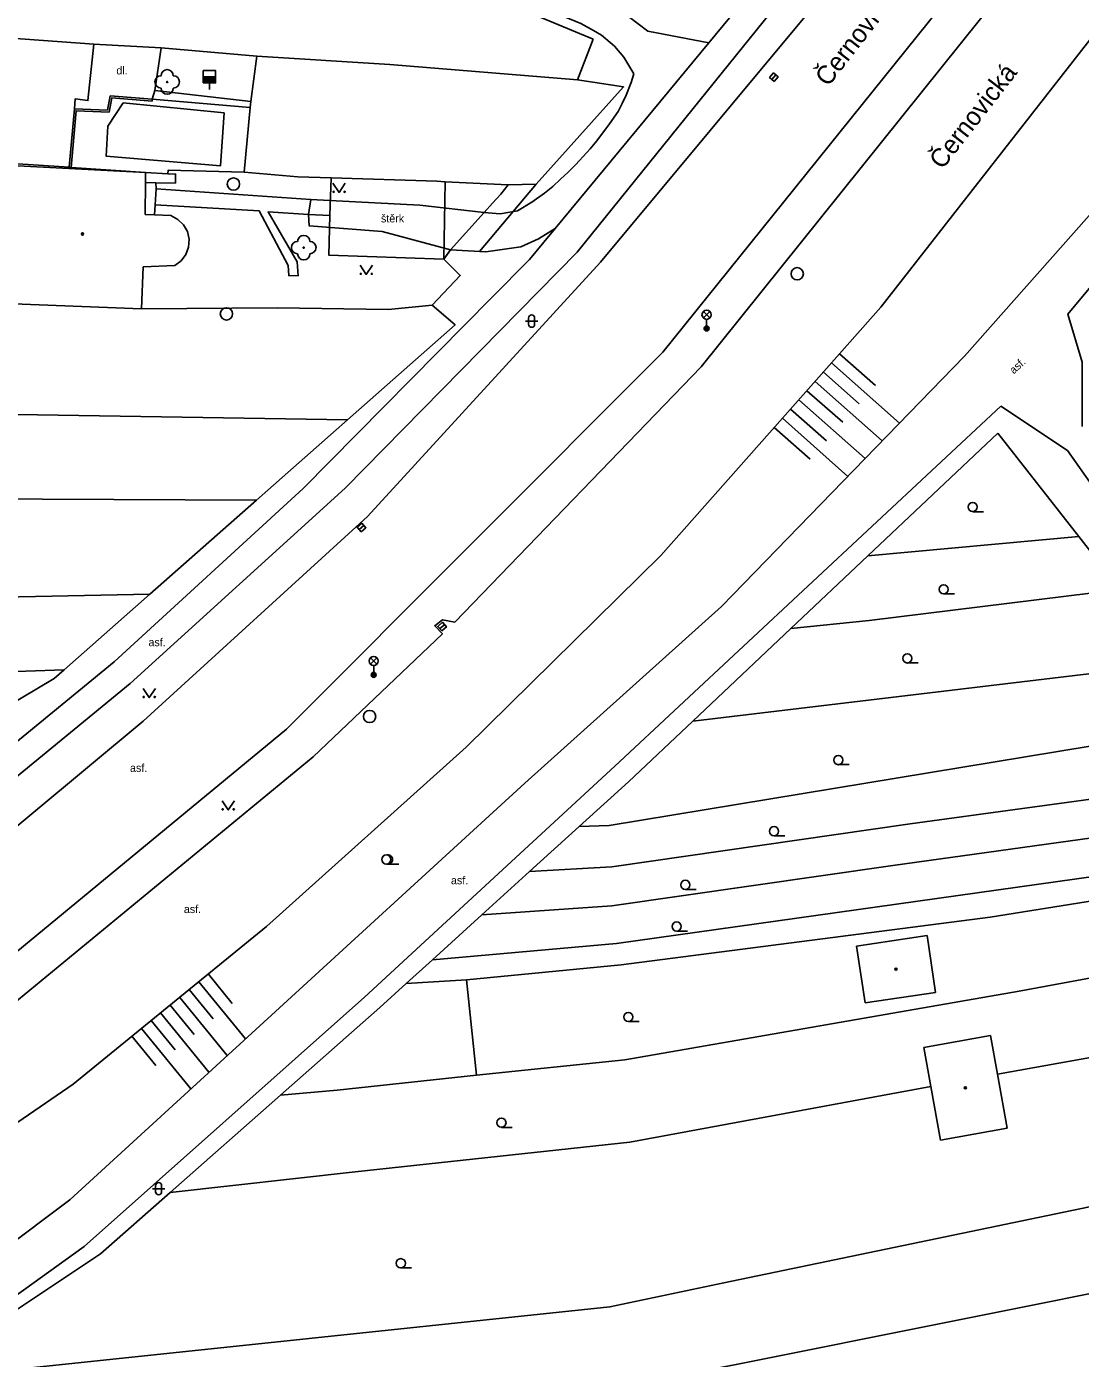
# Model space of a CAD drawing. Extents: x -596024 to -594475, y -1163820 to -1161957.
# Drawn here: x -595804.3 to -595718.6, y -1163179.9 to -1163071.7 of the extents above; entities that cross this region are included whole.
import ezdxf

# ---------------------------------------------------------------- set-up
doc = ezdxf.new("R2010")
doc.units = 0
for name, color, linetype in [('Level 10', 7, 'Continuous'), ('Level 11', 7, 'Continuous'), ('Level 15', 7, 'Continuous'), ('Level 22', 7, 'Continuous'), ('Level 27', 7, 'Continuous'), ('Level 28', 7, 'Continuous'), ('Level 33', 7, 'Continuous'), ('Level 36', 7, 'Continuous'), ('Level 39', 7, 'Continuous'), ('Level 40', 7, 'Continuous'), ('Level 49', 7, 'Continuous'), ('Level 5', 7, 'Continuous'), ('Level 51', 7, 'Continuous'), ('Level 7', 7, 'Continuous'), ('Level 8', 7, 'Continuous')]:
    doc.layers.add(name, color=color, linetype=linetype)

msp = doc.modelspace()

# ---------------------------------------------------------------- linework, layer by layer
at = {"layer": 'Level 10'}
for points in [[(-595731, -1163058.84), (-595757.62, -1163090.81), (-595776.56, -1163111.46), (-595794.79, -1163128.1), (-595813.08, -1163143.28), (-595835.32, -1163158.28), (-595856.17, -1163170.04), (-595881.68, -1163181.85), (-595895.55, -1163187.5), (-595919.36, -1163195.51)], [(-595721.7, -1163059.71), (-595727.41, -1163066.85), (-595752.54, -1163098.12), (-595783.15, -1163128.73), (-595808.42, -1163149.56), (-595821.75, -1163159.21), (-595852.05, -1163176.84), (-595874.52, -1163187.57), (-595889.03, -1163193.54), (-595907.96, -1163200.7)], [(-595851.62, -1163180.03), (-595852, -1163179.28), (-595851.17, -1163178.78), (-595850.24, -1163179.43), (-595816.94, -1163159.5), (-595817.13, -1163159.29), (-595816.41, -1163158.71), (-595816.25, -1163159.04), (-595807.1, -1163152.51), (-595807.94, -1163151.43), (-595807.25, -1163150.95), (-595805.84, -1163151.47), (-595780.97, -1163130.98), (-595770.46, -1163121), (-595771.09, -1163120.34), (-595770.47, -1163119.85), (-595769.45, -1163120.04), (-595749.44, -1163099.31), (-595723.41, -1163066.9), (-595719.38, -1163061.8)], [(-595715.01, -1163069.12), (-595734.82, -1163094.46), (-595752.71, -1163114.63), (-595768.54, -1163130.21), (-595784.76, -1163144.78), (-595800.47, -1163157.57), (-595824.03, -1163173.72), (-595844.1, -1163185.1), (-595871.39, -1163197.95), (-595902.45, -1163210.22)], [(-595707.55, -1163080.51), (-595719.62, -1163095.02), (-595718.47, -1163098.93), (-595718.47, -1163104.16)], [(-595756.45, -1163131.74), (-595725.06, -1163102.49)], [(-595725.06, -1163102.49), (-595719.66, -1163106.09)], [(-595719.66, -1163106.09), (-595715.38, -1163112.16), (-595709.01, -1163127.49)], [(-595776.81, -1163150.5), (-595756.45, -1163131.74)], [(-595799.59, -1163170.78), (-595776.81, -1163150.5)], [(-595825.62, -1163189.48), (-595799.59, -1163170.78)]]:
    msp.add_lwpolyline(points, dxfattribs=at)
at = {"layer": 'Level 11'}
for points in [[(-595748.82, -1163072.97), (-595734.72, -1163055.92)], [(-595733.15, -1163057.32), (-595759.5, -1163089.99), (-595778.37, -1163109.17), (-595795.84, -1163125.04), (-595814.68, -1163140.46), (-595836.38, -1163155.41), (-595857.69, -1163167.34), (-595883.05, -1163179.29), (-595896.6, -1163185.46), (-595919.59, -1163194.75), (-595919.36, -1163195.51)], [(-595786.65, -1163066.03), (-595775.08, -1163067.8), (-595764.22, -1163069.5), (-595761.52, -1163070.45), (-595759.2, -1163071.4), (-595758.18, -1163071.99), (-595757.54, -1163072.35), (-595756.49, -1163073.25), (-595755.73, -1163074.15), (-595755.31, -1163074.81), (-595754.91, -1163075.51)], [(-595786.29, -1163067.64), (-595764.61, -1163070.04), (-595758.22, -1163072.67)], [(-595753.76, -1163072.04), (-595755.35, -1163070.83), (-595756.68, -1163069.88), (-595757.77, -1163069.26)], [(-595758.22, -1163072.67), (-595759.49, -1163076)], [(-595753.76, -1163072.04), (-595748.82, -1163072.97)], [(-595800.38, -1163078.34), (-595800.31, -1163077.53), (-595799.28, -1163077.67), (-595798.81, -1163073.09)], [(-595793.32, -1163073.4), (-595793.83, -1163076.84)], [(-595761.3, -1163088.06), (-595748.82, -1163072.97)], [(-595896.52, -1163220.95), (-595869.19, -1163210.7), (-595854.29, -1163203.44), (-595828.89, -1163188.08), (-595800.76, -1163166.97), (-595763.77, -1163133.13), (-595747.79, -1163118.78), (-595728.03, -1163098.44), (-595711.98, -1163080.35), (-595706.35, -1163075.03)], [(-595754.91, -1163075.51), (-595755.12, -1163076.21), (-595755.52, -1163077.24), (-595755.84, -1163077.9), (-595756.19, -1163078.55), (-595756.87, -1163079.57), (-595757.91, -1163080.94), (-595758.46, -1163081.6), (-595759.62, -1163082.87), (-595760.23, -1163083.48), (-595760.86, -1163084.07), (-595761.5, -1163084.64), (-595762.16, -1163085.19)], [(-595794.05, -1163077.57), (-595793.83, -1163076.84)], [(-595793.83, -1163076.84), (-595786.04, -1163077.74)], [(-595796.41, -1163077.86), (-595788.21, -1163078.68), (-595788.51, -1163082.98), (-595797.79, -1163082.2), (-595797.67, -1163079.74), (-595796.41, -1163077.86)], [(-595786.08, -1163078.24), (-595794.05, -1163077.57)], [(-595793.76, -1163084.36), (-595794.61, -1163084.32)], [(-595792.79, -1163083.63), (-595792.16, -1163083.64), (-595792.17, -1163084.38), (-595793.76, -1163084.36)], [(-595793.76, -1163084.36), (-595793.74, -1163084.85)], [(-595770.35, -1163090.56), (-595779.7, -1163090.22), (-595779.61, -1163087), (-595779.52, -1163083.96)], [(-595770.35, -1163090.56), (-595770.23, -1163084.26)], [(-595767.45, -1163089.94), (-595762.85, -1163084.47)], [(-595793.81, -1163086.13), (-595793.74, -1163084.85)], [(-595793.74, -1163084.85), (-595781.15, -1163085.72)], [(-595762.16, -1163085.19), (-595763.21, -1163085.92), (-595764.37, -1163086.64), (-595765.77, -1163086.86), (-595767.06, -1163086.76)], [(-595793.81, -1163086.13), (-595793.88, -1163086.96)], [(-595781.34, -1163086.94), (-595784.64, -1163086.72), (-595782.27, -1163090.78), (-595782.2, -1163091.9), (-595782.95, -1163091.89), (-595783.01, -1163091.06), (-595785.36, -1163086.64), (-595793.81, -1163086.13)], [(-595781.34, -1163086.94), (-595781.15, -1163085.72)], [(-595767.06, -1163086.76), (-595772.31, -1163086.16), (-595779.61, -1163085.8), (-595781.15, -1163085.72)], [(-595781.34, -1163086.94), (-595781.3, -1163087.84), (-595775.37, -1163088.3), (-595769.8, -1163089.8)], [(-595781.34, -1163086.94), (-595779.61, -1163087)], [(-595920.12, -1163192.61), (-595897.38, -1163183.5), (-595884.17, -1163177.56), (-595867.38, -1163169.87), (-595837.49, -1163153.6), (-595815.9, -1163138.63), (-595797.14, -1163123.28), (-595781.78, -1163109.18), (-595766.48, -1163093.71), (-595763.38, -1163090.58), (-595762.22, -1163089.18), (-595761.3, -1163088.06)], [(-595769.8, -1163089.8), (-595766.93, -1163089.97), (-595764.08, -1163089.55), (-595762.65, -1163088.91), (-595761.3, -1163088.06)], [(-595923.03, -1163099.62), (-595851.06, -1163108.13), (-595814.6, -1163109.99), (-595785.58, -1163110.13)], [(-595831.04, -1163101.63), (-595815.16, -1163103.01), (-595778.18, -1163103.61)], [(-595925.48, -1163107.98), (-595916.18, -1163108.7), (-595898.85, -1163110.73), (-595850.52, -1163116.69), (-595814.21, -1163118.19), (-595794.24, -1163117.76)], [(-595718.74, -1163113.09), (-595735.88, -1163114.66)], [(-595920.85, -1163115.82), (-595870.62, -1163121.18), (-595850.22, -1163123.44), (-595837.87, -1163123.72), (-595813.71, -1163124.36), (-595801.21, -1163123.91)], [(-595742.13, -1163120.55), (-595735.77, -1163119.91), (-595715.36, -1163117.4)], [(-595712.26, -1163123.58), (-595750.12, -1163128.09)], [(-595759.36, -1163136.66), (-595756.9, -1163136.57), (-595715.19, -1163129.69), (-595710.3, -1163129.09)], [(-595763.38, -1163140.31), (-595756.69, -1163139.92), (-595732.44, -1163136.43), (-595714.17, -1163133.94)], [(-595767.25, -1163143.82), (-595756.7, -1163143.09), (-595733.86, -1163139.82), (-595714.71, -1163137.16)], [(-595771.27, -1163147.47), (-595756.31, -1163146.15), (-595715.62, -1163140.45)], [(-595717.47, -1163142.66), (-595725.94, -1163144.01), (-595755.93, -1163147.89), (-595768.5, -1163149.1)], [(-595768.5, -1163149.1), (-595773.4, -1163149.4)], [(-595768.5, -1163149.1), (-595767.69, -1163156.86)], [(-595767.69, -1163156.86), (-595755.65, -1163155.59), (-595723.59, -1163150.02)], [(-595767.69, -1163156.86), (-595779.03, -1163158.06), (-595783.63, -1163158.48)], [(-595792.6, -1163166.39), (-595777.57, -1163164.7), (-595755.23, -1163162.29), (-595730.77, -1163157.78)], [(-595813.31, -1163181.48), (-595805.74, -1163180.82), (-595756.85, -1163175.67), (-595747.6, -1163173.71)]]:
    msp.add_lwpolyline(points, dxfattribs=at)
at = {"layer": 'Level 15'}
for points in [[(-595735.27, -1163100.82), (-595738.18, -1163098.24)], [(-595736.6, -1163102.32), (-595739.5, -1163099.74)], [(-595733.32, -1163103.89), (-595738.84, -1163098.99)], [(-595734.72, -1163105.32), (-595740.17, -1163100.49)], [(-595737.92, -1163103.81), (-595740.83, -1163101.24)], [(-595739.25, -1163105.31), (-595742.16, -1163102.73)], [(-595736.11, -1163106.76), (-595741.49, -1163101.98)], [(-595737.51, -1163108.2), (-595742.82, -1163103.48)], [(-595740.58, -1163106.81), (-595743.49, -1163104.23)], [(-595786.48, -1163153.91), (-595790.27, -1163149.26)], [(-595787.55, -1163151.02), (-595789.49, -1163148.63)], [(-595787.96, -1163155.26), (-595791.82, -1163150.53)], [(-595789.1, -1163152.28), (-595791.04, -1163149.89)], [(-595790.65, -1163153.54), (-595792.59, -1163151.16)], [(-595792.2, -1163154.8), (-595794.14, -1163152.42)], [(-595789.44, -1163156.61), (-595793.37, -1163151.79)], [(-595793.75, -1163156.07), (-595795.7, -1163153.68)], [(-595790.92, -1163157.97), (-595794.92, -1163153.05)]]:
    msp.add_lwpolyline(points, dxfattribs=at)
at = {"layer": 'Level 22'}
for centre in [(-595792.84, -1163076.16), (-595781.74, -1163089.62)]:
    msp.add_circle(centre, 0.05, dxfattribs=at)
for centre, start, end in [((-595793.34, -1163076.16), 90, 270), ((-595792.84, -1163075.66), 0, 180), ((-595792.34, -1163076.16), 270, 90), ((-595792.84, -1163076.66), 180, 0), ((-595781.74, -1163089.12), 0, 180), ((-595782.24, -1163089.62), 90, 270), ((-595781.24, -1163089.62), 270, 90), ((-595781.74, -1163090.12), 180, 0)]:
    msp.add_arc(centre, 0.5, start, end, dxfattribs=at)
at = {"layer": 'Level 27'}
for p, q in [((-595743.68, -1163075.96), (-595743.36, -1163075.58)), ((-595777.23, -1163112.51), (-595776.85, -1163112.19)), ((-595770.68, -1163120.57), (-595770.3, -1163120.25))]:
    msp.add_line(p, q, dxfattribs=at)
for points in [[(-595743.5, -1163076.12), (-595743.17, -1163075.75), (-595743.54, -1163075.42), (-595743.87, -1163075.79)], [(-595777.06, -1163112.7), (-595776.69, -1163112.37), (-595777.02, -1163112), (-595777.39, -1163112.33)], [(-595770.51, -1163120.76), (-595770.14, -1163120.43), (-595770.47, -1163120.06), (-595770.84, -1163120.39)]]:
    msp.add_lwpolyline(points, close=True, dxfattribs=at)
for centre in [(-595787.45, -1163084.45), (-595741.62, -1163091.74), (-595788.02, -1163095), (-595776.38, -1163127.71)]:
    msp.add_circle(centre, 0.5, dxfattribs=at)
at = {"layer": 'Level 28'}
for p, q in [((-595789.91, -1163075.74), (-595788.91, -1163075.74)), ((-595789.91, -1163075.79), (-595788.91, -1163075.79)), ((-595789.91, -1163075.84), (-595788.91, -1163075.84)), ((-595789.91, -1163075.89), (-595788.91, -1163075.89)), ((-595789.91, -1163075.94), (-595788.91, -1163075.94)), ((-595789.91, -1163075.99), (-595788.91, -1163075.99)), ((-595789.91, -1163076.04), (-595788.91, -1163076.04)), ((-595789.91, -1163076.09), (-595788.91, -1163076.09)), ((-595789.91, -1163076.14), (-595788.91, -1163076.14)), ((-595789.91, -1163076.19), (-595788.91, -1163076.19)), ((-595789.41, -1163076.24), (-595789.41, -1163076.77))]:
    msp.add_line(p, q, dxfattribs=at)
msp.add_lwpolyline([(-595789.91, -1163076.24), (-595788.91, -1163076.24), (-595788.91, -1163075.24), (-595789.91, -1163075.24)], close=True, dxfattribs=at)
at = {"layer": 'Level 33'}
for p, q in [((-595749.25, -1163095.33), (-595748.72, -1163094.8)), ((-595749.25, -1163094.8), (-595748.72, -1163095.33)), ((-595748.99, -1163095.44), (-595748.99, -1163096.19)), ((-595776.32, -1163123.47), (-595775.79, -1163122.94)), ((-595776.32, -1163122.94), (-595775.79, -1163123.47)), ((-595776.05, -1163123.58), (-595776.05, -1163124.33))]:
    msp.add_line(p, q, dxfattribs=at)
for centre, radius in [((-595748.99, -1163095.07), 0.375), ((-595748.99, -1163096.19), 0.2), ((-595748.99, -1163096.19), 0.145), ((-595748.99, -1163096.19), 0.0876), ((-595776.05, -1163123.2), 0.375), ((-595776.05, -1163124.33), 0.2), ((-595776.05, -1163124.33), 0.145), ((-595776.05, -1163124.33), 0.0876)]:
    msp.add_circle(centre, radius, dxfattribs=at)
at = {"layer": 'Level 36'}
for p, q in [((-595763.47, -1163095.34), (-595763.47, -1163095.84)), ((-595762.97, -1163095.34), (-595762.97, -1163095.84)), ((-595763.72, -1163095.59), (-595762.72, -1163095.59)), ((-595727.36, -1163111.07), (-595726.48, -1163111.07)), ((-595729.72, -1163117.75), (-595728.84, -1163117.75)), ((-595732.67, -1163123.36), (-595731.8, -1163123.36)), ((-595738.28, -1163131.62), (-595737.41, -1163131.62)), ((-595743.51, -1163137.41), (-595742.64, -1163137.41)), ((-595775.02, -1163139.7), (-595774.02, -1163139.7)), ((-595750.72, -1163141.77), (-595749.84, -1163141.77)), ((-595751.42, -1163145.14), (-595750.55, -1163145.14)), ((-595755.35, -1163152.5), (-595754.48, -1163152.5)), ((-595765.67, -1163161.09), (-595764.8, -1163161.09)), ((-595794.04, -1163166.07), (-595793.04, -1163166.07)), ((-595793.79, -1163165.82), (-595793.79, -1163166.32)), ((-595793.29, -1163165.82), (-595793.29, -1163166.32)), ((-595773.85, -1163172.5), (-595772.98, -1163172.5))]:
    msp.add_line(p, q, dxfattribs=at)
for points in [[(-595779.36, -1163084.39), (-595778.86, -1163085.14), (-595778.36, -1163084.39)], [(-595777.15, -1163091.05), (-595776.65, -1163091.8), (-595776.15, -1163091.05)], [(-595794.8, -1163125.43), (-595794.3, -1163126.18), (-595793.8, -1163125.43)], [(-595788.38, -1163134.55), (-595787.88, -1163135.3), (-595787.38, -1163134.55)]]:
    msp.add_lwpolyline(points, dxfattribs=at)
for centre, radius in [((-595779.31, -1163085.09), 0.05), ((-595778.41, -1163085.09), 0.05), ((-595777.1, -1163091.75), 0.05), ((-595776.2, -1163091.75), 0.05), ((-595727.36, -1163110.69), 0.375), ((-595729.72, -1163117.38), 0.375), ((-595732.67, -1163122.99), 0.375), ((-595794.75, -1163126.13), 0.05), ((-595793.85, -1163126.13), 0.05), ((-595738.28, -1163131.25), 0.375), ((-595788.33, -1163135.25), 0.05), ((-595787.43, -1163135.25), 0.05), ((-595743.51, -1163137.03), 0.375), ((-595775.02, -1163139.33), 0.375), ((-595750.72, -1163141.39), 0.375), ((-595751.42, -1163144.77), 0.375), ((-595755.35, -1163152.12), 0.375), ((-595765.67, -1163160.71), 0.375), ((-595773.85, -1163172.13), 0.375)]:
    msp.add_circle(centre, radius, dxfattribs=at)
for centre, radius, start, end in [((-595763.22, -1163095.34), 0.25, 0, 180), ((-595763.22, -1163095.84), 0.25, 180, 0), ((-595774.89, -1163139.33), 0.375, 260.4059, 99.5941), ((-595793.54, -1163165.82), 0.25, 0, 180), ((-595793.54, -1163166.32), 0.25, 180, 0)]:
    msp.add_arc(centre, radius, start, end, dxfattribs=at)
at = {"layer": 'Level 39'}
for centre, radius in [((-595799.72, -1163088.52), 0.09), ((-595799.72, -1163088.52), 0.0398), ((-595733.59, -1163148.24), 0.09), ((-595733.59, -1163148.24), 0.0398), ((-595727.95, -1163157.88), 0.09), ((-595727.95, -1163157.88), 0.0398)]:
    msp.add_circle(centre, radius, dxfattribs=at)
at = {"layer": 'Level 5'}
for points in [[(-595804.99, -1163082.98), (-595794.6, -1163083.52)], [(-595794.6, -1163083.52), (-595794.61, -1163084.32)], [(-595794.61, -1163084.32), (-595794.64, -1163086.93)], [(-595794.64, -1163086.93), (-595793.88, -1163086.96)], [(-595793.88, -1163086.96), (-595792.53, -1163087.02)], [(-595792.53, -1163087.02), (-595791.97, -1163087.32)], [(-595791.97, -1163087.32), (-595791.51, -1163087.76)], [(-595791.51, -1163087.76), (-595791.2, -1163088.32)], [(-595791.2, -1163088.32), (-595791.06, -1163088.94)], [(-595791.1, -1163089.58), (-595791.32, -1163090.18)], [(-595791.06, -1163088.94), (-595791.1, -1163089.58)], [(-595792.21, -1163091.07), (-595794.8, -1163091.19)], [(-595791.7, -1163090.69), (-595792.21, -1163091.07)], [(-595791.32, -1163090.18), (-595791.7, -1163090.69)], [(-595794.8, -1163091.19), (-595794.93, -1163094.59)], [(-595794.93, -1163094.59), (-595808.12, -1163094.09)], [(-595736.8, -1163146.36), (-595731.06, -1163145.5)], [(-595731.06, -1163145.5), (-595730.37, -1163150.12)], [(-595736.11, -1163150.97), (-595736.8, -1163146.36)], [(-595730.37, -1163150.12), (-595736.11, -1163150.97)], [(-595731.34, -1163154.6), (-595725.91, -1163153.62)], [(-595725.91, -1163153.62), (-595725.34, -1163156.78)], [(-595730.77, -1163157.78), (-595731.34, -1163154.6)], [(-595725.34, -1163156.78), (-595724.55, -1163161.15)], [(-595729.98, -1163162.13), (-595730.77, -1163157.78)], [(-595724.55, -1163161.15), (-595729.98, -1163162.13)]]:
    msp.add_lwpolyline(points, dxfattribs=at)
at = {"layer": 'Level 51'}
for points in [[(-595702.2, -1163146.07), (-595723.59, -1163150.02)], [(-595699.94, -1163152.23), (-595725.34, -1163156.78)], [(-595695.71, -1163162.95), (-595747.6, -1163173.71)], [(-595762.04, -1163183.27), (-595746.73, -1163180.37), (-595693.16, -1163169.66)]]:
    msp.add_lwpolyline(points, dxfattribs=at)
at = {"layer": 'Level 7'}
for points in [[(-595815.57, -1163071.86), (-595798.81, -1163073.09)], [(-595798.81, -1163073.09), (-595793.32, -1163073.4)], [(-595793.32, -1163073.4), (-595785.55, -1163074.06)], [(-595785.55, -1163074.06), (-595786.04, -1163077.74)], [(-595785.55, -1163074.06), (-595774.74, -1163074.73), (-595759.49, -1163076)], [(-595759.49, -1163076), (-595755.74, -1163076.56), (-595762.85, -1163084.47), (-595765.11, -1163084.51)], [(-595794.05, -1163077.57), (-595794.06, -1163077.72), (-595797.35, -1163077.46), (-595797.56, -1163078.61), (-595800.24, -1163078.5), (-595800.65, -1163083.1)], [(-595800.38, -1163078.34), (-595797.7, -1163078.45), (-595797.47, -1163077.3), (-595794.05, -1163077.57)], [(-595800.8, -1163083.09), (-595800.38, -1163078.34)], [(-595786.08, -1163078.24), (-595786.58, -1163083.48)], [(-595824.22, -1163080.88), (-595804.99, -1163082.8), (-595800.8, -1163083.09)], [(-595800.65, -1163083.1), (-595800.8, -1163083.09)], [(-595800.65, -1163083.1), (-595794.6, -1163083.52)], [(-595792.79, -1163083.63), (-595794.6, -1163083.52)], [(-595786.58, -1163083.48), (-595792.75, -1163083.32), (-595792.79, -1163083.63)], [(-595765.11, -1163084.51), (-595770.23, -1163084.26), (-595770.92, -1163084.23), (-595779.52, -1163083.96), (-595782.21, -1163083.87), (-595786.58, -1163083.48)], [(-595765.11, -1163084.51), (-595765.73, -1163085.28)], [(-595766.39, -1163086), (-595767.06, -1163086.76)], [(-595769.8, -1163089.8), (-595770.35, -1163090.56), (-595769.02, -1163091.87), (-595771.31, -1163094.29)], [(-595771.31, -1163094.29), (-595774.86, -1163094.65), (-595783.89, -1163094.51), (-595794.93, -1163094.59)], [(-595771.31, -1163094.29), (-595769.43, -1163095.9), (-595778.18, -1163103.61)], [(-595778.18, -1163103.61), (-595785.58, -1163110.13)], [(-595735.88, -1163114.66), (-595725.32, -1163104.7)], [(-595725.32, -1163104.7), (-595718.74, -1163113.09)], [(-595785.58, -1163110.13), (-595794.24, -1163117.76)], [(-595718.74, -1163113.09), (-595715.36, -1163117.4)], [(-595742.13, -1163120.55), (-595735.88, -1163114.66)], [(-595794.24, -1163117.76), (-595801.21, -1163123.91)], [(-595750.12, -1163128.09), (-595742.13, -1163120.55)], [(-595801.21, -1163123.91), (-595802.03, -1163124.63), (-595814.05, -1163131.77)], [(-595755.35, -1163133.02), (-595750.12, -1163128.09)], [(-595759.36, -1163136.66), (-595755.35, -1163133.02)], [(-595763.38, -1163140.31), (-595759.36, -1163136.66)], [(-595767.25, -1163143.82), (-595763.38, -1163140.31)], [(-595771.27, -1163147.47), (-595767.25, -1163143.82)], [(-595773.4, -1163149.4), (-595771.27, -1163147.47)], [(-595775.56, -1163151.36), (-595773.4, -1163149.4)], [(-595783.63, -1163158.48), (-595775.56, -1163151.36)], [(-595792.6, -1163166.39), (-595783.63, -1163158.48)], [(-595798.25, -1163171.37), (-595792.6, -1163166.39)], [(-595809.99, -1163179.17), (-595798.25, -1163171.37)]]:
    msp.add_lwpolyline(points, dxfattribs=at)
at = {"layer": 'Level 8'}
for points in [[(-595786.08, -1163078.24), (-595786.04, -1163077.74)], [(-595766.39, -1163086), (-595765.73, -1163085.28)], [(-595769.8, -1163089.8), (-595767.06, -1163086.76)]]:
    msp.add_lwpolyline(points, dxfattribs=at)

# ---------------------------------------------------------------- texts
at = {"layer": 'Level 40'}
for s, p in [('dl.', (-595796.97, -1163075.55)), ('štěrk', (-595775.46, -1163087.57)), ('asf.', (-595794.36, -1163122)), ('asf.', (-595795.86, -1163132.21)), ('asf.', (-595769.77, -1163141.34)), ('asf.', (-595791.48, -1163143.68))]:
    msp.add_text(s, height=0.65, dxfattribs=at).set_placement(p)
msp.add_text('asf.', height=0.65, rotation=42.65, dxfattribs=at).set_placement((-595724.02, -1163099.93))
at = {"layer": 'Level 49'}
for p in [(-595739.11, -1163076.61), (-595729.83, -1163083.34)]:
    msp.add_text('Černovická', height=1.5, rotation=52.19, dxfattribs=at).set_placement(p)

doc.saveas('drawing.dxf')
